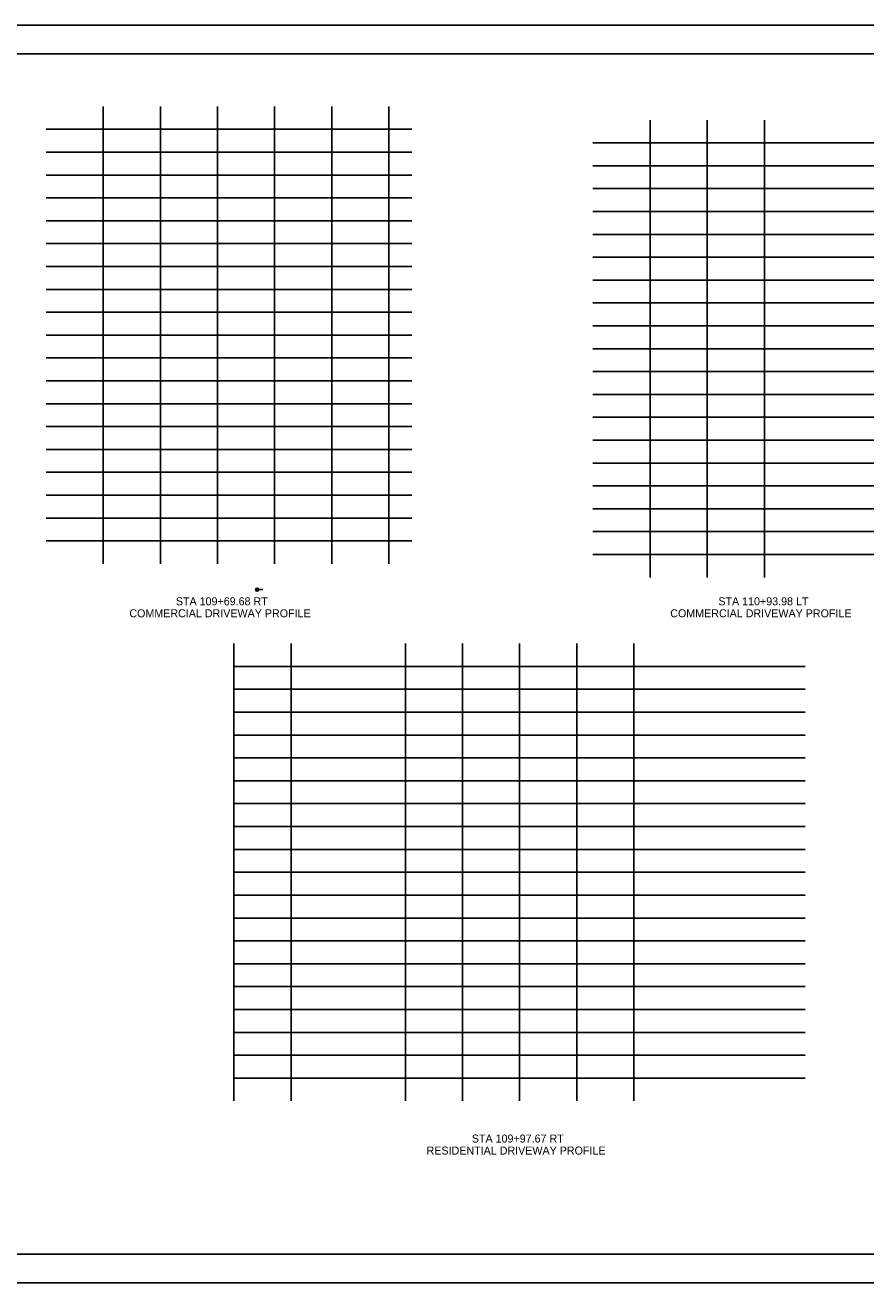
# Model space of a CAD drawing. Extents: x 0 to 461, y 0 to 110.
# Drawn here: x 67.6 to 141.2, y 0 to 110 of the extents above; entities that cross this region are included whole.
import ezdxf

# ---------------------------------------------------------------- set-up
doc = ezdxf.new("R2010")
doc.units = 0
for name, color, linetype in [('Default', 7, 'Continuous'), ('SH_Border', 7, 'Continuous'), ('SH_Cut_Line', 7, 'Continuous'), ('SH_Major_Grid_Line', 7, 'Continuous')]:
    doc.layers.add(name, color=color, linetype=linetype)

msp = doc.modelspace()

# ---------------------------------------------------------------- linework, layer by layer
at = {"layer": 'SH_Border'}
msp.add_lwpolyline([(7.5, 107.5), (167.5, 107.5), (167.5, 2.5), (7.5, 2.5)], close=True, dxfattribs=at)
at = {"layer": 'SH_Cut_Line'}
msp.add_lwpolyline([(0, 0), (170, 0), (170, 110), (0, 110)], close=True, dxfattribs=at)
at = {"layer": 'SH_Major_Grid_Line'}
for p, q in [((74.46, 62.89), (74.46, 102.89)), ((79.46, 62.89), (79.46, 102.89)), ((84.46, 62.89), (84.46, 102.89)), ((89.46, 62.89), (89.46, 102.89)), ((94.46, 62.89), (94.46, 102.89)), ((99.46, 62.89), (99.46, 102.89)), ((99.46, 62.89), (99.46, 102.89)), ((122.32, 61.7), (122.32, 101.7)), ((127.32, 61.7), (127.32, 101.7)), ((132.32, 61.7), (132.32, 101.7)), ((69.46, 100.89), (101.46, 100.89)), ((117.32, 99.7), (157.32, 99.7)), ((69.46, 98.89), (101.46, 98.89)), ((69.46, 96.89), (101.46, 96.89)), ((117.32, 97.7), (157.32, 97.7)), ((69.46, 94.89), (101.46, 94.89)), ((117.32, 95.7), (157.32, 95.7)), ((117.32, 93.7), (157.32, 93.7)), ((69.46, 92.89), (101.46, 92.89)), ((117.32, 91.7), (157.32, 91.7)), ((69.46, 90.89), (101.46, 90.89)), ((117.32, 89.7), (157.32, 89.7)), ((69.46, 88.89), (101.46, 88.89)), ((117.32, 87.7), (157.32, 87.7)), ((69.46, 86.89), (101.46, 86.89)), ((69.46, 84.89), (101.46, 84.89)), ((117.32, 85.7), (157.32, 85.7)), ((117.32, 83.7), (157.32, 83.7)), ((69.46, 82.89), (101.46, 82.89)), ((117.32, 81.7), (157.32, 81.7)), ((69.46, 80.89), (101.46, 80.89)), ((117.32, 79.7), (157.32, 79.7)), ((69.46, 78.89), (101.46, 78.89)), ((117.32, 77.7), (157.32, 77.7)), ((69.46, 76.89), (101.46, 76.89)), ((69.46, 74.89), (101.46, 74.89)), ((117.32, 75.7), (157.32, 75.7)), ((69.46, 72.89), (101.46, 72.89)), ((117.32, 73.7), (157.32, 73.7)), ((117.32, 71.7), (157.32, 71.7)), ((69.46, 70.89), (101.46, 70.89)), ((117.32, 69.7), (157.32, 69.7)), ((69.46, 68.89), (101.46, 68.89)), ((117.32, 67.7), (157.32, 67.7)), ((69.46, 66.89), (101.46, 66.89)), ((117.32, 65.7), (157.32, 65.7)), ((69.46, 64.89), (101.46, 64.89)), ((117.32, 63.7), (157.32, 63.7)), ((87.8, 60.63), (88.06, 60.63)), ((87.93, 60.63), (88.42, 60.63)), ((85.9, 15.91), (85.9, 55.91)), ((90.9, 15.91), (90.9, 55.91)), ((100.9, 15.91), (100.9, 55.91)), ((100.9, 15.91), (100.9, 55.91)), ((105.9, 15.91), (105.9, 55.91)), ((105.9, 15.91), (105.9, 55.91)), ((110.9, 15.91), (110.9, 55.91)), ((115.9, 15.91), (115.9, 55.91)), ((120.9, 15.91), (120.9, 55.91)), ((85.9, 53.91), (135.9, 53.91)), ((85.9, 51.91), (135.9, 51.91)), ((85.9, 49.91), (135.9, 49.91)), ((85.9, 47.91), (135.9, 47.91)), ((85.9, 45.91), (135.9, 45.91)), ((85.9, 43.91), (135.9, 43.91)), ((85.9, 41.91), (135.9, 41.91)), ((85.9, 39.91), (135.9, 39.91)), ((85.9, 37.91), (135.9, 37.91)), ((85.9, 35.91), (135.9, 35.91)), ((85.9, 33.91), (135.9, 33.91)), ((85.9, 31.91), (135.9, 31.91)), ((85.9, 29.91), (135.9, 29.91)), ((85.9, 27.91), (135.9, 27.91)), ((85.9, 25.91), (135.9, 25.91)), ((85.9, 23.91), (135.9, 23.91)), ((85.9, 21.91), (135.9, 21.91)), ((85.9, 19.91), (135.9, 19.91)), ((85.9, 17.91), (135.9, 17.91))]:
    msp.add_line(p, q, dxfattribs=at)
msp.add_circle((87.93, 60.63), 0.13, dxfattribs=at)

# ---------------------------------------------------------------- texts
at = {"layer": 'Default'}
for s, p in [('STA 109+69.68 RT', (80.82, 59.26)), ('STA 110+93.98 LT', (128.29, 59.26)), ('COMMERCIAL DRIVEWAY PROFILE', (76.75, 58.21)), ('COMMERCIAL DRIVEWAY PROFILE', (124.08, 58.21)), ('STA 109+97.67 RT', (106.72, 12.27)), ('RESIDENTIAL DRIVEWAY PROFILE', (102.76, 11.22))]:
    msp.add_text(s, height=0.7, dxfattribs=at).set_placement(p)
at = {"layer": 'SH_Major_Grid_Line'}
for s, p in [('21', (87.92, 60.58)), ('4', (87.93, 60.66)), ('CLP_Drive2 - Profile 2-1 [Sheet]', (88.1, 60.66)), ('1:5', (88.1, 60.58))]:
    msp.add_text(s, height=0.0164, dxfattribs=at).set_placement(p)

doc.saveas('drawing.dxf')
